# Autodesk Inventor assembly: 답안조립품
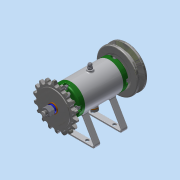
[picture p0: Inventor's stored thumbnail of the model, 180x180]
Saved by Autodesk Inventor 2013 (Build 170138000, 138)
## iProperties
Created: 2016-03
Part Number: 답안조립품
Document SubType Name: Assembly
Designer: Administrator
Author: Administrator
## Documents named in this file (16)
- C:\Users\Administrator\Desktop\460308V1010\답안조립품.iam
- C:\Users\Administrator\Desktop\460308V1010\1-본체.ipt
- C:\Users\Administrator\Desktop\460308V1010\커버.ipt
- C:\Users\Administrator\Desktop\460308V1010\베어링 15 x 32 x 9.ipt
- C:\Users\Administrator\Desktop\460308V1010\오일 실 15 25 7.ipt
- C:\Users\Administrator\Desktop\460308V1010\축.ipt
- C:\Users\Administrator\Desktop\460308V1010\볼트 M4 x 12.ipt
- C:\Users\Administrator\Desktop\460308V1010\키 3 x 3 x 12.ipt
- C:\Users\Administrator\Desktop\460308V1010\V벨트풀리.ipt
- C:\Users\Administrator\Desktop\460308V1010\스프로킷.ipt
- C:\Users\Administrator\Desktop\460308V1010\와셔 8x17.ipt
- C:\Users\Administrator\Desktop\460308V1010\와셔 6x11.5.ipt
- C:\Users\Administrator\Desktop\460308V1010\볼트 M 6 x 8.ipt
- C:\Users\Administrator\Desktop\460308V1010\니플 M 6 x 0.75.ipt
- C:\Users\Administrator\Desktop\460308V1010\스프링와셔 8.ipt
- C:\Users\Administrator\Desktop\460308V1010\너트 M 8.ipt
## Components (12 placed, 4 different names)
1. 1-본체:1
2. KS B 2023 6002 - 15 x 32 x 9:1
3. KS B 2023 6002 - 15 x 32 x 9:2
4. V벨트풀리:1 — 각도:4
5. ISO 4762 M4 x 12:1
6. ISO 4762 M4 x 12:3
7. ISO 4762 M4 x 12:4
8. ISO 4762 M4 x 12:5
9. ISO 4762 M4 x 12:2
10. ISO 4762 M4 x 12:6
11. ISO 4762 M4 x 12:7
12. ISO 4762 M4 x 12:8
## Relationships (1: Angle 1)
- 각도:4 [Angle]: V벨트풀리:1
